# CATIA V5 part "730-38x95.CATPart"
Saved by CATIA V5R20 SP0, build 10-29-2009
Part number: 730-38x95
Definition: NONE
Nomenclature: 730-38x95
Source: Unknown
Description: 730-38x95
Bounding box of the stored display mesh (mm): x -23 to 23, y -22.5 to 22.5, z 0 to 95
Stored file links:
  C:\Users\Utente\Desktop\IO LAVORO\3D X SITO CF\X SITO\730\730-38x95.CATPart
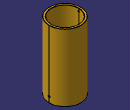
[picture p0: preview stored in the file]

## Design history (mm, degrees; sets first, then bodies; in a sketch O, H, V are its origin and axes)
Body1 "730-38x95" (main body)
  Solid1: solid without history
